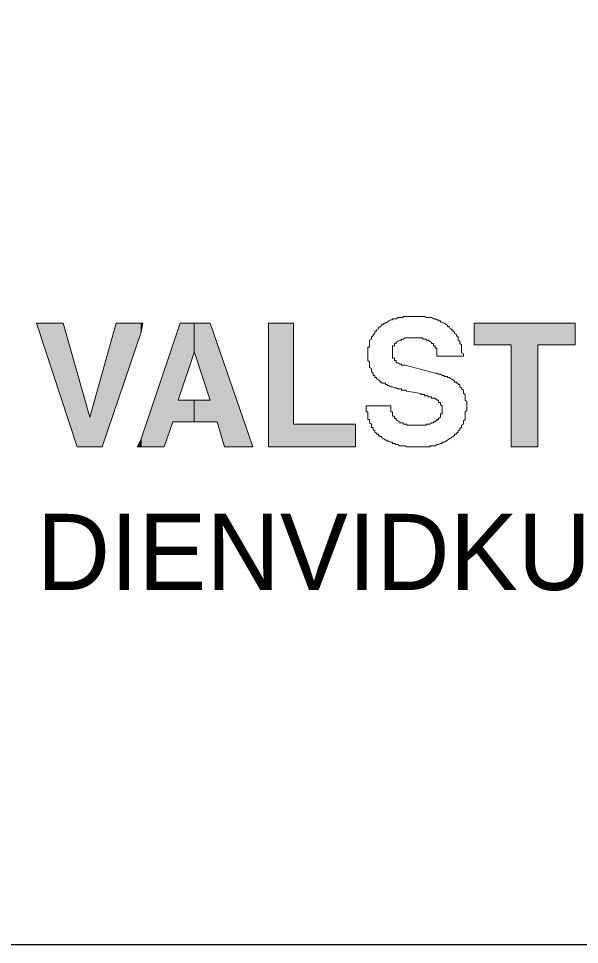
# Model space of a CAD drawing. Extents: x 308460 to 314812, y 245206 to 253414.
# Drawn here: x 314375.1 to 314471.8, y 245324.6 to 245484.2 of the extents above; entities that cross this region are included whole.
import ezdxf

# ---------------------------------------------------------------- set-up
doc = ezdxf.new("R2010")
doc.units = 0
doc.header["$LTSCALE"] = 8.4
doc.layers.add('57', color=7, linetype='Continuous', lineweight=13)

msp = doc.modelspace()

# ---------------------------------------------------------------- hatches: boundary and pattern name
at = {"layer": '57'}
for points in [[(314387.404, 245415.46), (314391.984, 245431.682), (314396.259, 245431.682), (314396.259, 245430.115), (314389.546, 245410.375), (314385.271, 245410.375), (314378.254, 245431.682), (314382.834, 245431.682)], [(314405.404, 245426.602), (314402.667, 245418.392), (314405.404, 245418.392), (314405.404, 245414.68), (314401.749, 245414.68), (314400.219, 245410.375), (314396.259, 245410.375), (314396.259, 245411.74), (314402.964, 245431.682), (314405.404, 245431.682)], [(314396.259, 245430.115), (314396.259, 245431.682), (314396.562, 245431.682)], [(314405.404, 245426.8), (314405.404, 245431.682), (314408.139, 245431.682), (314415.474, 245410.375), (314410.594, 245410.375), (314409.376, 245414.68), (314405.404, 245414.68), (314405.404, 245418.392), (314408.139, 245418.392)], [(314422.494, 245431.682), (314422.494, 245414.287), (314433.169, 245414.287), (314433.169, 245410.375), (314418.229, 245410.375), (314418.229, 245431.682)], [(314464.594, 245427.97), (314464.594, 245410.375), (314460.027, 245410.375), (314460.027, 245427.97), (314453.622, 245427.97), (314453.622, 245431.682), (314470.999, 245431.682), (314470.999, 245427.97)], [(314396.259, 245410.375), (314395.651, 245410.375), (314396.259, 245411.74)]]:
    msp.add_hatch(color=256, dxfattribs=at).paths.add_polyline_path(points)

# ---------------------------------------------------------------- linework, layer by layer
at = {"layer": '57', "lineweight": 25}
msp.add_lwpolyline([(314811.502, 253140.399), (311999.871, 253140.399), (311999.871, 245324.593), (314811.502, 245324.593)], close=True, dxfattribs=at)
at = {"layer": '57'}
for points in [[(314437.749, 245421.31), (314437.749, 245421.517), (314437.452, 245421.517), (314437.452, 245421.7), (314437.141, 245421.9), (314436.826, 245422.09), (314436.826, 245422.297), (314436.534, 245422.297), (314436.534, 245422.488), (314436.534, 245422.675), (314436.214, 245422.675), (314436.214, 245422.882), (314436.214, 245423.07), (314435.926, 245423.268), (314435.926, 245423.455), (314435.926, 245423.662), (314435.926, 245423.857), (314435.607, 245424.048), (314435.607, 245424.247), (314435.607, 245424.442), (314435.607, 245424.637), (314435.607, 245424.828), (314435.607, 245425.03), (314435.304, 245425.218), (314435.304, 245425.413), (314435.304, 245425.62), (314435.304, 245425.81), (314435.304, 245426.002), (314435.304, 245426.193), (314435.304, 245426.4), (314435.304, 245426.587), (314435.304, 245426.782), (314435.304, 245426.973), (314435.304, 245427.18), (314435.304, 245427.378), (314435.304, 245427.562), (314435.607, 245427.562), (314435.607, 245427.765), (314435.607, 245427.955), (314435.607, 245428.155), (314435.607, 245428.342), (314435.607, 245428.548), (314435.607, 245428.743), (314435.926, 245428.93), (314435.926, 245429.133), (314435.926, 245429.325), (314436.214, 245429.523), (314436.214, 245429.71), (314436.534, 245429.913), (314436.534, 245430.108), (314436.534, 245430.3), (314436.826, 245430.3), (314436.826, 245430.505), (314437.141, 245430.693), (314437.141, 245430.892), (314437.452, 245431.083), (314437.749, 245431.282), (314437.749, 245431.48), (314438.056, 245431.48), (314438.056, 245431.668), (314438.359, 245431.668), (314438.667, 245431.86), (314438.952, 245432.062), (314439.271, 245432.26), (314439.582, 245432.26), (314439.582, 245432.448), (314439.882, 245432.448), (314440.201, 245432.448), (314440.489, 245432.655), (314440.797, 245432.655), (314441.116, 245432.655), (314441.404, 245432.655), (314441.404, 245432.845), (314441.719, 245432.845), (314442.016, 245432.845), (314442.327, 245432.845), (314442.624, 245432.845), (314442.939, 245432.845), (314443.242, 245432.845), (314443.549, 245432.845), (314443.849, 245432.845), (314444.161, 245432.845), (314444.461, 245432.845), (314444.769, 245432.845), (314445.069, 245432.845), (314445.379, 245432.655), (314445.676, 245432.655), (314445.987, 245432.655), (314446.287, 245432.655), (314446.599, 245432.448), (314446.899, 245432.448), (314447.194, 245432.26), (314447.509, 245432.26), (314447.509, 245432.062), (314447.809, 245432.062), (314447.809, 245431.86), (314448.129, 245431.86), (314448.432, 245431.668), (314448.724, 245431.48), (314449.044, 245431.282), (314449.044, 245431.083)], [(314449.044, 245431.083), (314449.332, 245431.083), (314449.332, 245430.892), (314449.651, 245430.693), (314449.651, 245430.505), (314449.959, 245430.505), (314449.959, 245430.3), (314450.259, 245430.108), (314450.259, 245429.913), (314450.566, 245429.71), (314450.566, 245429.523), (314450.866, 245429.325), (314450.866, 245429.133), (314450.866, 245428.93), (314450.866, 245428.743), (314451.177, 245428.548), (314451.177, 245428.342), (314451.177, 245428.155), (314451.474, 245427.955), (314451.474, 245427.765), (314451.474, 245427.562), (314451.474, 245427.378), (314451.474, 245427.18), (314451.474, 245426.973), (314451.474, 245426.782), (314451.474, 245426.587), (314451.777, 245426.4), (314451.777, 245426.193), (314451.777, 245426.002), (314447.194, 245426.002), (314447.194, 245426.193), (314447.194, 245426.4), (314447.194, 245426.587), (314447.194, 245426.782), (314447.194, 245426.973), (314447.194, 245427.18), (314447.194, 245427.378), (314446.899, 245427.378), (314446.899, 245427.562), (314446.899, 245427.765), (314446.599, 245427.765), (314446.599, 245427.955), (314446.599, 245428.155), (314446.287, 245428.155), (314446.287, 245428.342), (314445.987, 245428.548), (314445.676, 245428.743), (314445.379, 245428.743), (314445.379, 245428.93), (314445.069, 245428.93), (314444.769, 245428.93), (314444.769, 245429.133), (314444.461, 245429.133), (314444.161, 245429.133), (314443.849, 245429.133), (314443.549, 245429.133), (314443.242, 245429.133), (314442.939, 245429.133), (314442.624, 245429.133), (314442.327, 245429.133), (314442.016, 245429.133), (314441.719, 245429.133), (314441.404, 245428.93), (314441.116, 245428.93), (314441.116, 245428.743), (314440.797, 245428.743), (314440.489, 245428.548), (314440.201, 245428.342), (314440.201, 245428.155), (314439.882, 245428.155), (314439.882, 245427.955), (314439.882, 245427.765), (314439.582, 245427.765), (314439.582, 245427.562), (314439.582, 245427.378), (314439.582, 245427.18), (314439.582, 245426.973), (314439.582, 245426.782), (314439.582, 245426.587), (314439.582, 245426.4), (314439.582, 245426.193), (314439.582, 245426.002), (314439.582, 245425.81), (314439.582, 245425.62), (314439.882, 245425.62), (314439.882, 245425.413), (314439.882, 245425.218), (314440.201, 245425.218), (314440.201, 245425.03), (314440.201, 245424.828), (314440.489, 245424.828), (314440.797, 245424.637), (314441.116, 245424.637), (314441.116, 245424.442), (314441.404, 245424.442), (314441.719, 245424.442), (314446.899, 245423.07), (314447.194, 245423.07), (314447.509, 245422.882), (314447.809, 245422.882), (314448.129, 245422.675)], [(314435.014, 245417.407), (314439.271, 245417.407), (314439.271, 245417.205), (314439.271, 245417.017), (314439.271, 245416.818), (314439.271, 245416.627), (314439.271, 245416.42), (314439.582, 245416.42), (314439.582, 245416.225), (314439.582, 245416.038), (314439.582, 245415.847), (314439.582, 245415.645), (314439.882, 245415.645), (314439.882, 245415.45), (314439.882, 245415.258), (314440.201, 245415.258), (314440.201, 245415.055), (314440.489, 245414.865), (314440.797, 245414.673), (314440.797, 245414.478), (314441.116, 245414.478), (314441.404, 245414.478), (314441.404, 245414.275), (314441.719, 245414.275), (314442.016, 245414.275), (314442.016, 245414.088), (314442.327, 245414.088), (314442.624, 245414.088), (314442.939, 245414.088), (314443.242, 245414.088), (314443.549, 245414.088), (314443.849, 245414.088), (314444.161, 245414.088), (314444.461, 245414.088), (314444.769, 245414.088), (314445.069, 245414.088), (314445.379, 245414.088), (314445.379, 245414.275), (314445.676, 245414.275), (314445.987, 245414.275), (314446.287, 245414.478), (314446.599, 245414.478), (314446.599, 245414.673), (314446.899, 245414.673), (314446.899, 245414.865), (314447.194, 245414.865), (314447.194, 245415.055), (314447.509, 245415.055), (314447.509, 245415.258), (314447.809, 245415.45), (314447.809, 245415.645), (314447.809, 245415.847), (314447.809, 245416.038), (314448.129, 245416.038), (314448.129, 245416.225), (314448.129, 245416.42), (314448.129, 245416.627), (314448.129, 245416.818), (314448.129, 245417.017), (314448.129, 245417.205), (314448.129, 245417.407), (314447.809, 245417.605), (314447.809, 245417.79), (314447.809, 245417.995), (314447.509, 245417.995), (314447.509, 245418.187), (314447.509, 245418.385), (314447.194, 245418.385), (314447.194, 245418.585), (314446.899, 245418.585), (314446.899, 245418.775), (314446.599, 245418.775), (314446.287, 245418.775), (314446.287, 245418.97), (314445.987, 245418.97), (314445.676, 245418.97), (314445.676, 245419.162), (314445.379, 245419.162), (314445.069, 245419.162), (314445.069, 245419.36), (314444.769, 245419.36), (314444.461, 245419.36), (314444.461, 245419.56), (314442.016, 245419.938), (314441.719, 245420.14), (314441.404, 245420.14), (314441.116, 245420.14), (314441.116, 245420.332), (314440.797, 245420.332), (314440.489, 245420.332), (314440.201, 245420.53), (314439.882, 245420.53), (314439.582, 245420.722), (314439.271, 245420.722), (314438.952, 245420.92), (314438.667, 245420.92), (314438.667, 245421.12), (314438.359, 245421.12), (314438.359, 245421.31), (314438.056, 245421.31), (314437.749, 245421.31)], [(314448.129, 245422.675), (314448.432, 245422.675), (314448.432, 245422.488), (314448.724, 245422.488), (314449.044, 245422.488), (314449.044, 245422.297), (314449.332, 245422.297), (314449.651, 245422.09), (314449.959, 245421.9), (314450.259, 245421.7), (314450.259, 245421.517), (314450.566, 245421.517), (314450.566, 245421.31), (314450.866, 245421.31), (314450.866, 245421.12), (314451.177, 245421.12), (314451.177, 245420.92), (314451.177, 245420.722), (314451.474, 245420.53), (314451.474, 245420.332), (314451.777, 245420.14), (314451.777, 245419.938), (314451.777, 245419.75), (314451.777, 245419.56), (314452.089, 245419.36), (314452.089, 245419.162), (314452.089, 245418.97), (314452.089, 245418.775), (314452.089, 245418.585), (314452.089, 245418.385), (314452.392, 245418.187), (314452.392, 245417.995), (314452.392, 245417.79), (314452.392, 245417.605), (314452.392, 245417.407), (314452.392, 245417.205), (314452.392, 245417.017), (314452.392, 245416.818), (314452.392, 245416.627), (314452.089, 245416.42), (314452.089, 245416.225), (314452.089, 245416.038), (314452.089, 245415.847), (314452.089, 245415.645), (314452.089, 245415.45), (314452.089, 245415.258), (314452.089, 245415.055), (314451.777, 245414.865), (314451.777, 245414.673), (314451.777, 245414.478), (314451.777, 245414.275), (314451.474, 245414.088), (314451.474, 245413.89), (314451.474, 245413.687), (314451.177, 245413.5), (314451.177, 245413.305), (314450.866, 245413.11), (314450.866, 245412.907), (314450.566, 245412.715), (314450.566, 245412.525), (314450.259, 245412.525), (314450.259, 245412.318), (314449.959, 245412.13), (314449.651, 245411.932), (314449.332, 245411.745), (314449.044, 245411.538), (314448.724, 245411.35), (314448.432, 245411.152), (314448.129, 245411.152), (314448.129, 245410.953), (314447.809, 245410.953), (314447.509, 245410.762), (314447.194, 245410.762), (314446.899, 245410.563), (314446.599, 245410.563), (314446.287, 245410.563), (314445.987, 245410.563), (314445.987, 245410.375), (314445.676, 245410.375), (314445.379, 245410.375), (314445.069, 245410.375), (314444.769, 245410.375), (314444.461, 245410.375), (314444.161, 245410.375), (314443.849, 245410.375), (314443.549, 245410.375), (314443.242, 245410.375), (314442.939, 245410.375), (314442.624, 245410.375), (314442.327, 245410.375), (314442.016, 245410.375), (314441.719, 245410.563), (314441.404, 245410.563), (314441.116, 245410.563), (314440.797, 245410.563), (314440.489, 245410.762), (314440.201, 245410.762), (314439.882, 245410.953), (314439.582, 245410.953), (314439.582, 245411.152), (314439.271, 245411.152)], [(314439.271, 245411.152), (314438.952, 245411.35), (314438.667, 245411.35), (314438.667, 245411.538), (314438.359, 245411.538), (314438.056, 245411.745), (314437.749, 245411.932), (314437.749, 245412.13), (314437.452, 245412.13), (314437.141, 245412.318), (314437.141, 245412.525), (314436.826, 245412.525), (314436.826, 245412.715), (314436.534, 245412.907), (314436.534, 245413.11), (314436.214, 245413.305), (314436.214, 245413.5), (314436.214, 245413.687), (314435.926, 245413.687), (314435.926, 245413.89), (314435.926, 245414.088), (314435.926, 245414.275), (314435.607, 245414.478), (314435.607, 245414.673), (314435.607, 245414.865), (314435.607, 245415.055), (314435.304, 245415.055), (314435.304, 245415.258), (314435.304, 245415.45), (314435.304, 245415.645), (314435.304, 245415.847), (314435.304, 245416.038), (314435.304, 245416.225), (314435.304, 245416.42), (314435.014, 245416.42), (314435.014, 245416.627), (314435.014, 245416.818), (314435.014, 245417.017), (314435.014, 245417.205), (314435.014, 245417.407)]]:
    msp.add_lwpolyline(points, dxfattribs=at)
for points in [[(314387.404, 245415.46), (314391.984, 245431.682), (314396.259, 245431.682), (314396.259, 245430.115), (314389.546, 245410.375), (314385.271, 245410.375), (314378.254, 245431.682), (314382.834, 245431.682)], [(314405.404, 245426.602), (314402.667, 245418.392), (314405.404, 245418.392), (314405.404, 245414.68), (314401.749, 245414.68), (314400.219, 245410.375), (314396.259, 245410.375), (314396.259, 245411.74), (314402.964, 245431.682), (314405.404, 245431.682)], [(314396.259, 245430.115), (314396.259, 245431.682), (314396.562, 245431.682)], [(314405.404, 245426.8), (314405.404, 245431.682), (314408.139, 245431.682), (314415.474, 245410.375), (314410.594, 245410.375), (314409.376, 245414.68), (314405.404, 245414.68), (314405.404, 245418.392), (314408.139, 245418.392)], [(314422.494, 245431.682), (314422.494, 245414.287), (314433.169, 245414.287), (314433.169, 245410.375), (314418.229, 245410.375), (314418.229, 245431.682)], [(314464.594, 245427.97), (314464.594, 245410.375), (314460.027, 245410.375), (314460.027, 245427.97), (314453.622, 245427.97), (314453.622, 245431.682), (314470.999, 245431.682), (314470.999, 245427.97)], [(314396.259, 245410.375), (314395.651, 245410.375), (314396.259, 245411.74)]]:
    msp.add_lwpolyline(points, close=True, dxfattribs=at)

# ---------------------------------------------------------------- texts
msp.add_text('DIENVIDKURZEMES', height=13.12, dxfattribs=at).set_placement((314378.253, 245385.698))

doc.saveas('drawing.dxf')
